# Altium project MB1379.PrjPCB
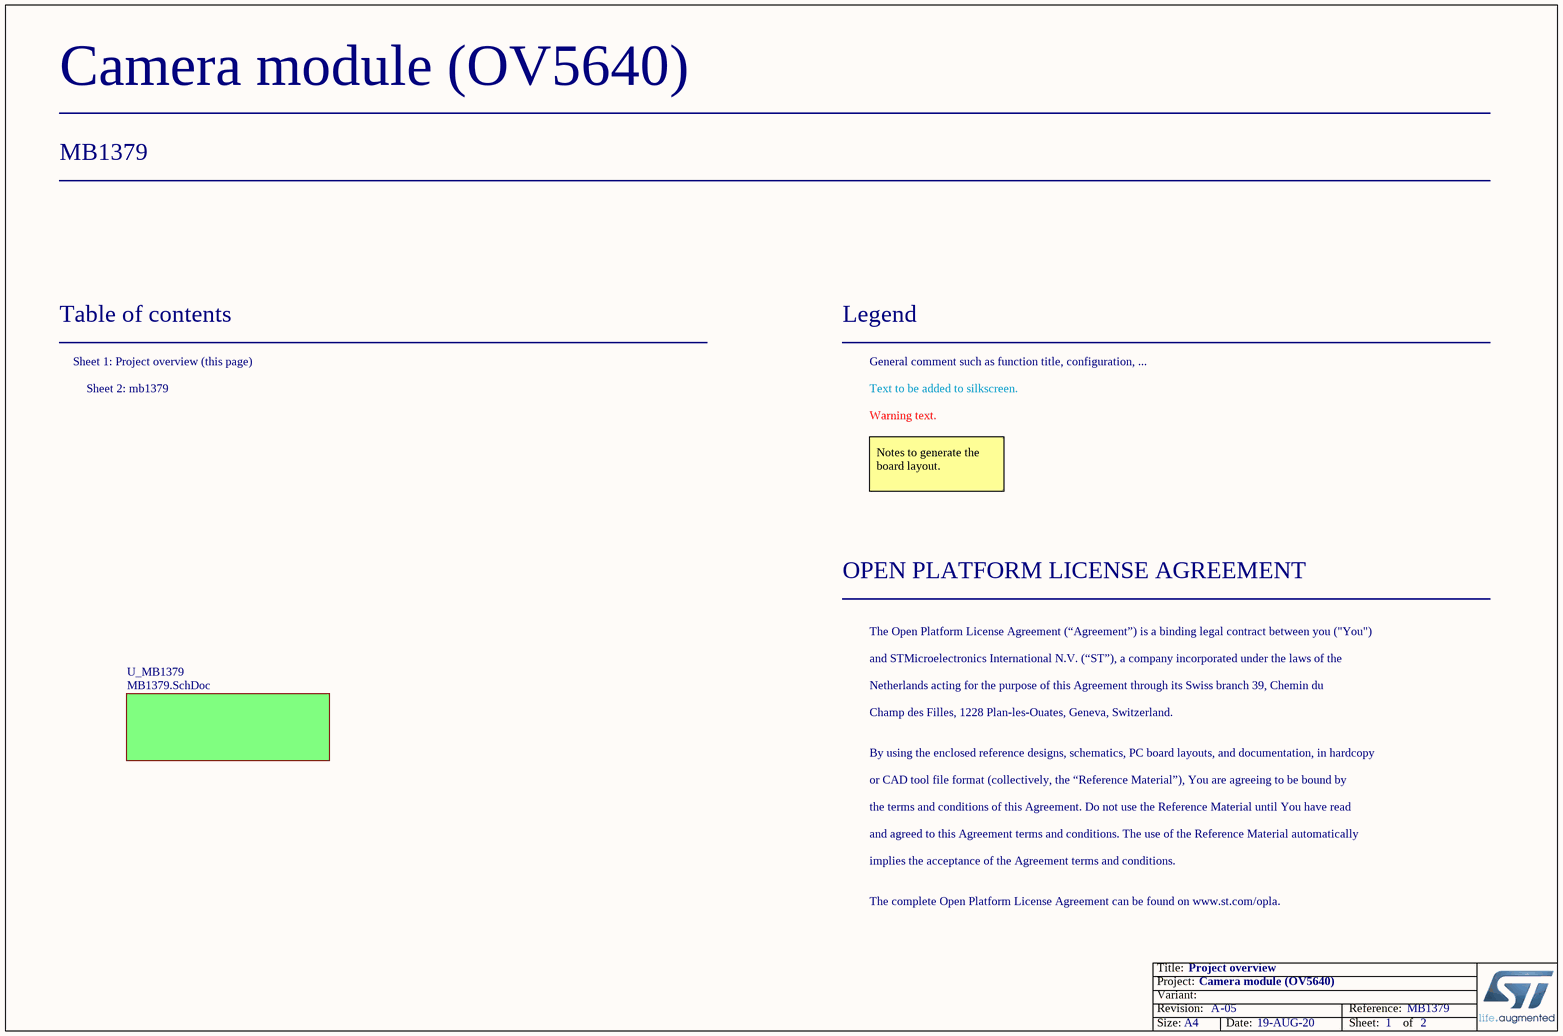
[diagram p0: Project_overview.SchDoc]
Board_Reference: MB1379; Board_PCB_Revision: A; Board_Name: Camera module (OV5640); Board_Document_Date: 19-AUG-20; Board_BOM_Revision: 05; Board_Assembly_Revision: 05
2 sheets, 40 parts. Net scope: global (net labels, ports and power ports of the same name join across sheets).
Board file: MB1379.PcbDoc
Sheets:
  Project_overview.SchDoc
    U_MB1379 = MB1379.SchDoc

## Sheet Project_overview.SchDoc: Project overview
size A4; Date: Not used; ApprovedBy: Not used; CheckedBy: Not used; Author: Not used; CompanyName: STMicroelectronics; DrawnBy: Not used; Engineer: Not used; Organization: Not used; Address1: Not used; Address2: Not used; Address3: Not used; Address4: Not used; DocumentNumber: 1; Revision: Not used; SheetNumber: 1; SheetTotal: 2

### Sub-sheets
U_MB1379 = MB1379.SchDoc: no entries

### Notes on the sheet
- Table of contents
- Sheet 1: Project overview (this page)
- Legend
- General comment such as function title, configuration, ...
- Sheet 2: mb1379
- Text to be added to silkscreen.
- Warning text.
- Notes to generate the board layout.
- OPEN PLATFORM LICENSE AGREEMENT
- The Open Platform License Agreement (“Agreement”) is a binding legal contract between you ("You")
- and STMicroelectronics International N.V. (“ST”), a company incorporated under the laws of the
- Netherlands acting for the purpose of this Agreement through its Swiss branch 39, Chemin du
- Champ des Filles, 1228 Plan-les-Ouates, Geneva, Switzerland.
- By using the enclosed reference designs, schematics, PC board layouts, and documentation, in hardcopy
- or CAD tool file format (collectively, the “Reference Material”), You are agreeing to be bound by
- the terms and conditions of this Agreement. Do not use the Reference Material until You have read
- and agreed to this Agreement terms and conditions. The use of the Reference Material automatically
- implies the acceptance of the Agreement terms and conditions.
- The complete Open Platform License Agreement can be found on www.st.com/opla.

## Sheet MB1379.SchDoc: Camera Module :HDF5640-AF-V2.0
size A4; Date: Not used; ApprovedBy: Not used; CheckedBy: Not used; Author: Not used; CompanyName: STMicroelectronics; DrawnBy: Not used; Engineer: Not used; Organization: Not used; Address1: Not used; Address2: Not used; Address3: Not used; Address4: Not used; DocumentNumber: Not used; Revision: Not used; SheetNumber: 2; SheetTotal: 2
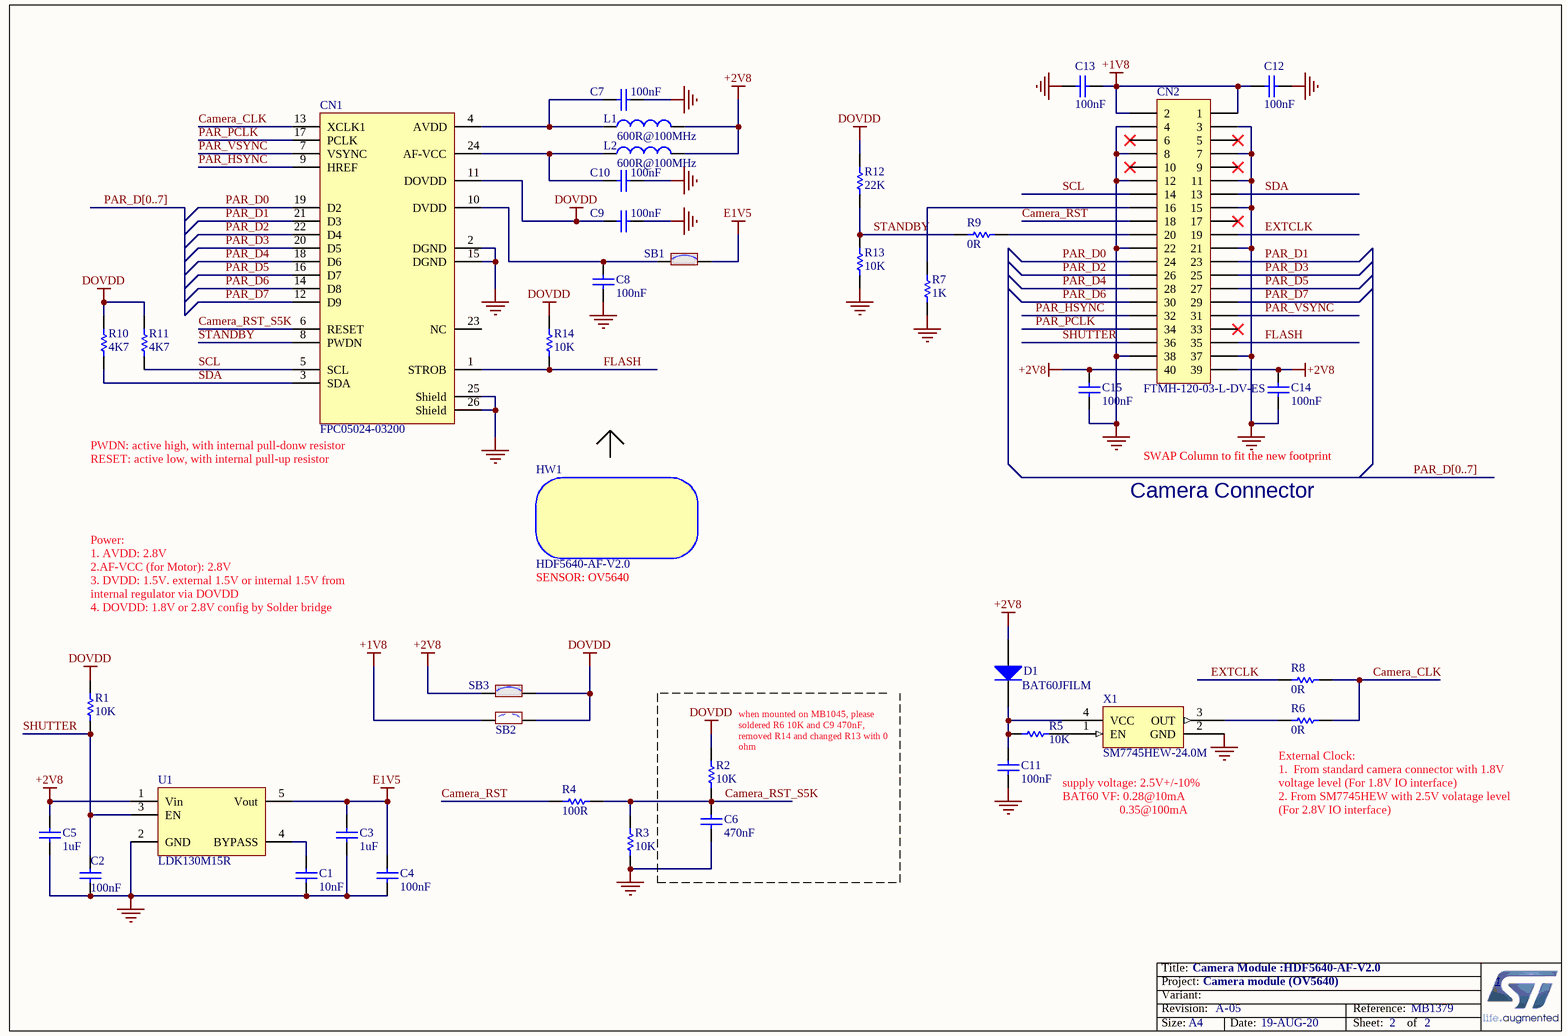
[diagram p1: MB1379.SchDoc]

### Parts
C1  value 10nF  [C0603]  (hidden comment: Capacitor)
C2  value 100nF  [C0603]  (hidden comment: Capacitor)
C3  value 1uF  [C0603]  (hidden comment: Capacitor)
C4  value 100nF  [C0603]  (hidden comment: Capacitor)
C5  value 1uF  [C0603]  (hidden comment: Capacitor)
C6  value 470nF  [C0603]  (hidden comment: Capacitor)
C7  value 100nF  [C0603]  (hidden comment: Capacitor)
C8  value 100nF  [C0603]  (hidden comment: Capacitor)
C9  value 100nF  [C0603]  (hidden comment: Capacitor)
C10  value 100nF  [C0603]  (hidden comment: Capacitor)
C11  value 100nF  [C0603]  (hidden comment: Capacitor)
C12  value 100nF  [C0603]  (hidden comment: Capacitor)
C13  value 100nF  [C0603]  (hidden comment: Capacitor)
C14  value 100nF  [C0603]  (hidden comment: Capacitor)
C15  value 100nF  [C0603]  (hidden comment: Capacitor)
CN1  FPC05024-03200  [CON_ATOM_FPC05024-03200]
CN2  value FTMH-120-03-L-DV-ES  [CON_SAMTEC_FTMH-120-03-L-DV-ES]  (hidden comment: Header 20x2)
D1  BAT60JFILM  [DIO_SOD323]
HW1  value HDF5640-AF-V2.0  (hidden comment: Camera_Module)
L1  value 600R@100MHz  [L0603]  (hidden comment: BEAD)
L2  value 600R@100MHz  [L0603]  (hidden comment: BEAD)
R1  value 10K  [R0603]  (hidden comment: Resistor)
R2  value 10K  [R0603]  (hidden comment: Resistor)
R3  value 10K  [R0603]  (hidden comment: Resistor)
R4  value 100R  [R0603]  (hidden comment: Resistor)
R5  value 10K  [R0603]  (hidden comment: Resistor)
R6  value 0R  [R0603]  (hidden comment: Resistor)
R7  value 1K  [R0603]  (hidden comment: Resistor)
R8  value 0R  [R0603]  (hidden comment: Resistor)
R9  value 0R  [R0603]  (hidden comment: Resistor)
R10  value 4K7  [R0603]  (hidden comment: Resistor)
R11  value 4K7  [R0603]  (hidden comment: Resistor)
R12  value 22K  [R0603]  (hidden comment: Resistor)
R13  value 10K  [R0603]  (hidden comment: Resistor)
R14  value 10K  [R0603]  (hidden comment: Resistor)
SB1  SB_ON  [SOLDER-BRIDGE_R0603-0R]  (value not drawn)
SB2  SB_OFF  [SOLDER-BRIDGE_R0603-0R]  (value not drawn)
SB3  SB_ON  [SOLDER-BRIDGE_R0603-0R]  (value not drawn)
U1  LDK130M15R  [REG_SOT23-5L]
X1  value SM7745HEW-24.0M  [OSC_PLE_SM77H-SERIES_7X5_H1P73_4P]  (hidden comment: SM7745HEV-24.0M)

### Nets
+1V8: C12.1 C13.2 CN2.1 CN2.2 SB2.1
+2V8: C5.2 C14.2 C15.2 CN2.39 CN2.40 D1.1(A) L1.2 L2.2 SB3.1 U1.1(Vin)
DOVDD: C9.1 CN1.11(DOVDD) R1.2 R2.2 R10.1 R11.1 R12.2 R14.2 SB2.2 SB3.2
E1V5: C3.2 C4.2 SB1.2 U1.5(Vout)
GND: C1.1 C2.1 C3.1 C4.1 C5.1 C6.1 C7.2 C8.1 C9.2 C10.2 C11.1 C12.2 C13.1 C14.1 C15.1 CN1.2(DGND) CN1.15(DGND) CN1.25(Shield) CN1.26(Shield) CN2.3 CN2.4 CN2.7 CN2.8 CN2.11 CN2.12 CN2.15 CN2.21 CN2.22 CN2.37 CN2.38 R3.1 R7.2 R13.1 U1.2(GND) X1.2(GND)
Camera_CLK: CN1.13(XCLK1) R6.2 R8.2
Camera_RST: CN2.18 R4.1
Camera_RST_S5K: C6.2 CN1.6(RESET) R2.1 R3.2 R4.2
EXTCLK: CN2.19 R8.1
FLASH: CN1.1(STROB) CN2.35 R14.1
PAR_D0: CN1.19(D2) CN2.24
PAR_D1: CN1.21(D3) CN2.23
PAR_D2: CN1.22(D4) CN2.26
PAR_D3: CN1.20(D5) CN2.25
PAR_D4: CN1.18(D6) CN2.28
PAR_D5: CN1.16(D7) CN2.27
PAR_D6: CN1.14(D8) CN2.30
PAR_D7: CN1.12(D9) CN2.29
PAR_HSYNC: CN1.9(HREF) CN2.32
PAR_PCLK: CN1.17(PCLK) CN2.34
PAR_VSYNC: CN1.7(VSYNC) CN2.31
SCL: CN1.5(SCL) CN2.14 R11.2
SDA: CN1.3(SDA) CN2.13 R10.2
SHUTTER: C2.2 CN2.36 R1.1 U1.3(EN)
STANDBY: CN1.8(PWDN) R9.1 R12.1 R13.2
NetC1_2: C1.2 U1.4(BYPASS)
NetC7_1: C7.1 CN1.4(AVDD) L1.1
NetC8_2: C8.2 CN1.10(DVDD) SB1.1
NetC10_1: C10.1 CN1.24(AF-VCC) L2.1
NetC11_2: C11.2 D1.2(K) R5.2 X1.4(VCC)
NetCN2_16: CN2.16 R7.1
NetCN2_20: CN2.20 R9.2
NetR5_1: R5.1 X1.1(EN)
NetR6_1: R6.1 X1.3(OUT)

Not connected (* = marked no-connect by the designer): CN1 23(NC); CN2 5* 6* 9* 10* 17* 33*

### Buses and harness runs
bus PAR_D[0..7]

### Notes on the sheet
- (near CN1) PWDN: active high, with internal pull-donw resistor
  RESET: active low, with internal pull-up resistor
- Camera Connector
- SWAP Column to fit the new footprint
- SENSOR: OV5640
- Power:
  1. AVDD: 2.8V
  2.AF-VCC (for Motor): 2.8V
  3. DVDD: 1.5V. external 1.5V or internal 1.5V from internal regulator via DOVDD
  4. DOVDD: 1.8V or 2.8V config by Solder bridge
- (near R2) when mounted on MB1045, please soldered R6 10K and C9 470nF, removed R14 and changed R13 with 0 ohm
- supply voltage: 2.5V+/-10%
  BAT60 VF: 0.28@10mA
  0.35@100mA
- (near R6) External Clock:
  1.  From standard camera connector with 1.8V voltage level (For 1.8V IO interface)
  2. From SM7745HEW with 2.5V volatage level (For 2.8V IO interface)
- 1

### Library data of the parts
C1 = MCD-01007: Capacitor, MLCC, 10nF, 16V, X7R, 10%, 0603, T=0.8mm; Manufacturer_Part_Number: CC0603KRX7R7BB103; Manufacturer: YAGEO; Provided_By: SUBCO
C2 C4 C7-C15 = MCD-00211: Capacitor, MLCC, 100nF, 16V, X7R, 10%, 0603, T=0,8mm; Manufacturer_Part_Number: CC0603KRX7R7BB104; Manufacturer: YAGEO; ECCN_US: EAR99; ECCN_EU: NEC; Provided_By: SUBCO
C3 C5 = MCD-00010: Capacitor, MLCC, 1uF, 16V, X5R, 10%, 0603, T=0,8mm; Manufacturer_Part_Number: CC0603KRX5R7BB105; Manufacturer: YAGEO; ECCN_US: EAR99; ECCN_EU: NEC; Provided_By: SUBCO
C6 = MCD-01006: Capacitor, MLCC, 470nF, 16V, X7R, 10%, 0603, T=0.8mm; Manufacturer_Part_Number: CC0603KRX7R7BB474; Manufacturer: YAGEO; Provided_By: SUBCO
CN1 = MCD-01009: FFC/FPC ZIF Connector - 0.5mm, 24 pins, Upper Contacts; Manufacturer: ATOM; Provided_By: SUBCO
CN2 = MCD-01010: Header 20x2, 1mm, Dual Vertical,SMT,End Shroud,Height 3.25mm; Part_Type: Connector; Manufacturer: SAMTEC; Provided_By: SUBCO
D1 = MCD-00034: Manufacturer: STMICROELECTRONICS; Part_Type: Diode; BMS_Part_Number: 9151097; ECCN_US: EAR99; ECCN_EU: NEC; Provided_By: SUBCO with ST control
HW1 = MCD-01012: Camera Module with OV5640; Part_Type: Misc; Manufacturer: SHENZHEN V-VISION TECHNOLOGY CO. LTD; Alternate_Manufacturer: OEM; Provided_By: SUBCO
L1 L2 = MCD-00047: SMD Chip ferrite bead, 600R@100MHz +/-25%, 350mA, 500mohm DC, 0603, T=0.8mm; Part_Type: Inductor; Manufacturer_Part_Number: FCM1608KF-601T03; Manufacturer: TAI-TECH; Provided_By: SUBCO
R1-R3 R5 R13 R14 = MCD-00220: Resistor,10K,0603,1%,1/10W; Manufacturer_Part_Number: RC0603FR-0710KL; Manufacturer: YAGEO; ECCN_US: EAR99; ECCN_EU: NEC; Provided_By: SUBCO
R4 = MCD-00224: Resistor,100R,0603,1%,1/10W; Manufacturer_Part_Number: RC0603FR-07100RL; Manufacturer: YAGEO; Alternate_Manufacturer_Part_Number: RT0402FRE07100KL; Part_Preference: Recommended; ECCN_US: EAR99; ECCN_EU: NEC; Provided_By: SUBCO
R6 R8 R9 = MCD-00056: Resistor,0R,0603,5%,1/10W; Manufacturer_Part_Number: RC0603JR-070RL; Manufacturer: YAGEO; ECCN_US: EAR99; ECCN_EU: NEC; Provided_By: SUBCO
R7 = MCD-00070: Resistor,1K,0603,1%,1/10W; Manufacturer_Part_Number: RC0603FR-071KL; Manufacturer: YAGEO; Alternate_Manufacturer_Part_Number: RT0402FRE07100KL; ECCN_US: EAR99; ECCN_EU: NEC; Provided_By: SUBCO
R10 R11 = MCD-00219: Resistor,4K7,0603,1%,1/10W; Manufacturer_Part_Number: RC0603FR-074K7L; Manufacturer: YAGEO; ECCN_US: EAR99; ECCN_EU: NEC; Provided_By: SUBCO
R12 = MCD-00430: Resistor,22K,0603,1%,1/10W; Manufacturer_Part_Number: RC0603FR-0722KL; Manufacturer: YAGEO; ECCN_US: EAR99; ECCN_EU: NEC; Provided_By: SUBCO
SB1 SB3 = MCD-00071: Solder Bridge ON; Part_Type: Mechanical; Manufacturer: YAGEO; Manufacturer_Part_Number: RC0603JR-070RL; Provided_By: SUBCO
SB2 = MCD-00072: Solder Bridge OFF; Part_Type: Mechanical; Manufacturer: YAGEO; Manufacturer_Part_Number: RC0603JR-070RL; Provided_By: SUBCO
U1 = MCD-01008: LDO - 300 mA low quiescent current - very low noise; Part_Type: IC; Manufacturer: STMICROELECTRONICS; ECCN_US: EAR99; ECCN_EU: NEC; Provided_By: SUBCO with ST control
X1 = MCD-01011: SM77H Series 2.5V  CMOS 24MHz Clock Oscillator; Part_Type: Crystal_Osc; Manufacturer: PLETRONICS; Provided_By: SUBCO

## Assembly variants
2V8: not fitted C6 R2 R3 R8 R10 R11 R12 R13 R14 SB2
